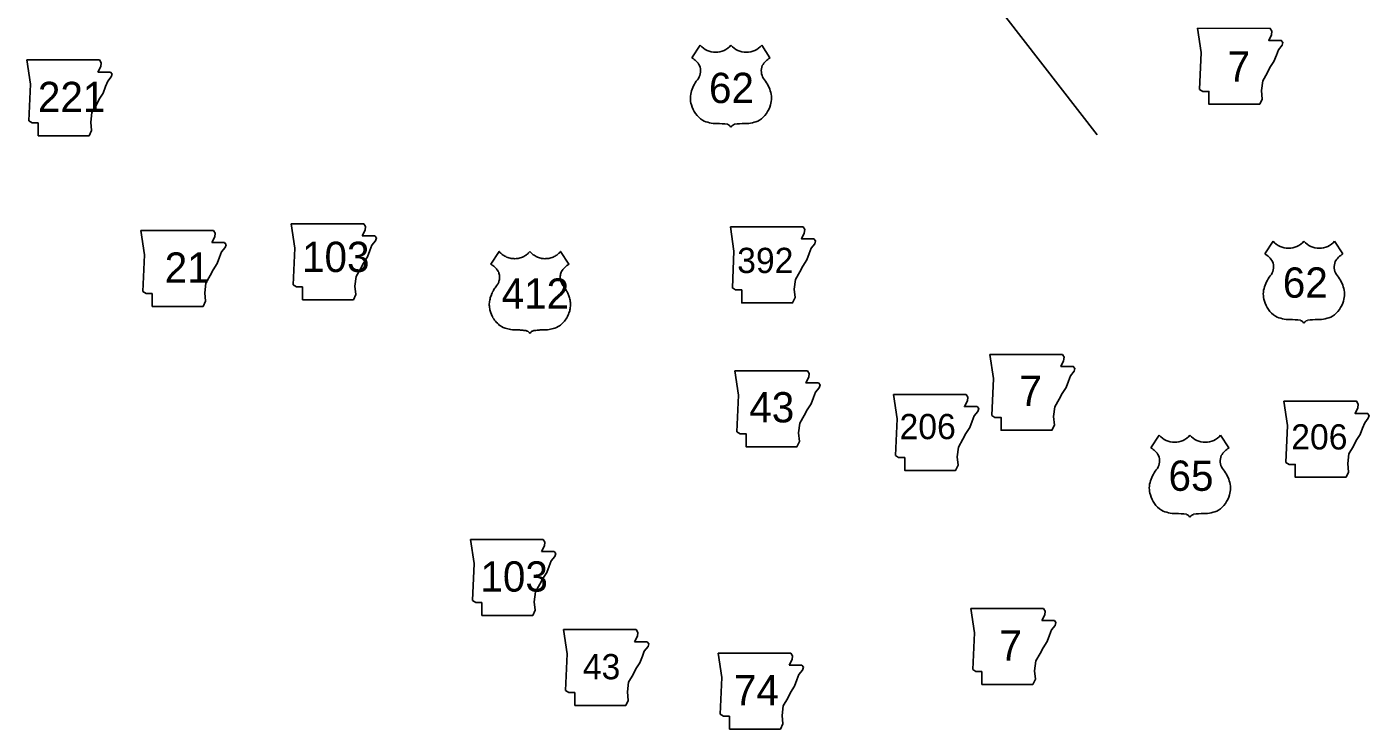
# Model space of a CAD drawing. Extents: x -819161 to 80911, y -6604 to 768454.
# Drawn here: x 41298 to 43405, y 4694 to 5796 of the extents above; entities that cross this region are included whole.
import ezdxf

# ---------------------------------------------------------------- set-up
doc = ezdxf.new("R2010")
doc.units = 0
for name, color, linetype in [('Default', 7, 'Continuous'), ('Level 21', 7, 'Continuous'), ('Level 22', 7, 'Continuous')]:
    doc.layers.add(name, color=color, linetype=linetype)

msp = doc.modelspace()

# ---------------------------------------------------------------- linework, layer by layer
at = {"layer": 'Default'}
msp.add_lwpolyline([(42312.2, 6485.2), (42978.2, 5626.8)], dxfattribs=at)
at = {"layer": 'Level 21'}
for p, q in [((41297.9, 5744.4), (41303.6, 5706.4)), ((41409.5, 5725.4), (41414, 5734.3)), ((41414.6, 5740), (41412, 5744.4)), ((41414, 5734.3), (41414.6, 5740)), ((41429.2, 5725.4), (41409.5, 5725.4)), ((41424.8, 5710.8), (41430.5, 5717.8)), ((41431.7, 5722.2), (41429.2, 5725.4)), ((41430.5, 5717.8), (41431.7, 5722.2)), ((41303.6, 5706.4), (41301, 5648.6)), ((41411.4, 5682.9), (41417.8, 5692.4)), ((41417.8, 5692.4), (41421.6, 5702.6)), ((41421.6, 5702.6), (41424.8, 5710.8)), ((41400, 5662), (41407, 5674)), ((41407, 5674), (41411.4, 5682.9)), ((41301, 5648.6), (41306.1, 5645.5)), ((41398.1, 5646.7), (41400, 5662)), ((41306.1, 5645.5), (41315.6, 5645.5)), ((41315.6, 5645.5), (41315.6, 5625.2)), ((41395.6, 5625.2), (41399.4, 5633.4)), ((41399.4, 5633.4), (41398.1, 5646.7)), ((41315.6, 5625.2), (41395.6, 5625.2)), ((41712.9, 5487.1), (41718.6, 5449)), ((41829.6, 5482.7), (41827, 5487.1)), ((41829, 5477), (41829.6, 5482.7)), ((41476.8, 5476.6), (41482.5, 5438.6)), ((41588.5, 5457.6), (41592.9, 5466.5)), ((41593.5, 5472.2), (41590.9, 5476.6)), ((41592.9, 5466.5), (41593.5, 5472.2)), ((41824.6, 5468.1), (41829, 5477)), ((41844.2, 5468.1), (41824.6, 5468.1)), ((41839.8, 5453.5), (41845.5, 5460.5)), ((41846.8, 5464.9), (41844.2, 5468.1)), ((41845.5, 5460.5), (41846.8, 5464.9)), ((41482.5, 5438.6), (41480, 5380.8)), ((41608.1, 5457.6), (41588.5, 5457.6)), ((41600.5, 5434.8), (41603.7, 5443)), ((41603.7, 5443), (41609.4, 5450)), ((41610.7, 5454.4), (41608.1, 5457.6)), ((41609.4, 5450), (41610.7, 5454.4)), ((41718.6, 5449), (41716.1, 5391.3)), ((41832.8, 5435.1), (41836.6, 5445.2)), ((41836.6, 5445.2), (41839.8, 5453.5)), ((41590.4, 5415.1), (41596.7, 5424.6)), ((41596.7, 5424.6), (41600.5, 5434.8)), ((41815, 5404.6), (41822, 5416.7)), ((41822, 5416.7), (41826.5, 5425.6)), ((41826.5, 5425.6), (41832.8, 5435.1)), ((41579, 5394.2), (41585.9, 5406.2)), ((41585.9, 5406.2), (41590.4, 5415.1)), ((41813.1, 5389.4), (41815, 5404.6)), ((41480, 5380.8), (41485.1, 5377.7)), ((41485.1, 5377.7), (41494.6, 5377.7)), ((41494.6, 5377.7), (41494.6, 5357.4)), ((41577.1, 5378.9), (41579, 5394.2)), ((41578.3, 5365.6), (41577.1, 5378.9)), ((41716.1, 5391.3), (41721.2, 5388.1)), ((41721.2, 5388.1), (41730.7, 5388.1)), ((41730.7, 5388.1), (41730.7, 5367.8)), ((41810.6, 5367.8), (41814.4, 5376.1)), ((41814.4, 5376.1), (41813.1, 5389.4)), ((41494.6, 5357.4), (41574.5, 5357.4)), ((41574.5, 5357.4), (41578.3, 5365.6)), ((41730.7, 5367.8), (41810.6, 5367.8)), ((41994.4, 4991.7), (42000.1, 4953.7)), ((42106.1, 4972.7), (42110.5, 4981.6)), ((42111.1, 4987.3), (42108.5, 4991.7)), ((42110.5, 4981.6), (42111.1, 4987.3)), ((42000.1, 4953.7), (41997.6, 4895.9)), ((42125.7, 4972.7), (42106.1, 4972.7)), ((42118.1, 4949.9), (42121.3, 4958.1)), ((42121.3, 4958.1), (42127, 4965.1)), ((42128.3, 4969.5), (42125.7, 4972.7)), ((42127, 4965.1), (42128.3, 4969.5)), ((42108, 4930.2), (42114.3, 4939.7)), ((42114.3, 4939.7), (42118.1, 4949.9)), ((42096.6, 4909.3), (42103.5, 4921.3)), ((42103.5, 4921.3), (42108, 4930.2)), ((41997.6, 4895.9), (42002.7, 4892.8)), ((42002.7, 4892.8), (42012.2, 4892.8)), ((42012.2, 4892.8), (42012.2, 4872.5)), ((42094.6, 4894), (42096.6, 4909.3)), ((42095.9, 4880.7), (42094.6, 4894)), ((42012.2, 4872.5), (42092.1, 4872.5)), ((42092.1, 4872.5), (42095.9, 4880.7)), ((42779.9, 4883.3), (42785.6, 4845.3)), ((42891.5, 4864.3), (42896, 4873.2)), ((42896.6, 4878.9), (42894, 4883.3)), ((42896, 4873.2), (42896.6, 4878.9)), ((42140.6, 4850.2), (42146.3, 4812.1)), ((42257.3, 4845.7), (42254.7, 4850.1)), ((42911.2, 4864.3), (42891.5, 4864.3)), ((42903.6, 4841.5), (42906.8, 4849.7)), ((42906.8, 4849.7), (42912.5, 4856.7)), ((42913.7, 4861.1), (42911.2, 4864.3)), ((42912.5, 4856.7), (42913.7, 4861.1)), ((42252.2, 4831.1), (42256.7, 4840)), ((42271.9, 4831.1), (42252.2, 4831.1)), ((42256.7, 4840), (42257.3, 4845.7)), ((42274.4, 4827.9), (42271.9, 4831.1)), ((42273.2, 4823.5), (42274.4, 4827.9)), ((42785.6, 4845.3), (42783.1, 4787.5)), ((42893.4, 4821.8), (42899.8, 4831.3)), ((42899.8, 4831.3), (42903.6, 4841.5)), ((42146.3, 4812.1), (42143.7, 4754.4)), ((42260.5, 4798.1), (42264.3, 4808.3)), ((42264.3, 4808.3), (42267.4, 4816.5)), ((42267.4, 4816.5), (42273.2, 4823.5)), ((42383.4, 4813.2), (42389.1, 4775.1)), ((42500.1, 4808.8), (42497.5, 4813.1)), ((42499.5, 4803), (42500.1, 4808.8)), ((42882, 4800.9), (42889, 4812.9)), ((42889, 4812.9), (42893.4, 4821.8)), ((42249.7, 4779.7), (42254.1, 4788.6)), ((42254.1, 4788.6), (42260.5, 4798.1)), ((42495, 4794.2), (42499.5, 4803)), ((42514.7, 4794.2), (42495, 4794.2)), ((42510.2, 4779.6), (42516, 4786.5)), ((42517.2, 4791), (42514.7, 4794.2)), ((42516, 4786.5), (42517.2, 4791)), ((42783.1, 4787.5), (42788.1, 4784.4)), ((42788.1, 4784.4), (42797.6, 4784.4)), ((42797.6, 4784.4), (42797.6, 4764.1)), ((42880.1, 4785.6), (42882, 4800.9)), ((42881.4, 4772.3), (42880.1, 4785.6)), ((42240.8, 4752.4), (42242.7, 4767.7)), ((42242.7, 4767.7), (42249.7, 4779.7)), ((42389.1, 4775.1), (42386.5, 4717.4)), ((42503.3, 4761.2), (42507.1, 4771.3)), ((42507.1, 4771.3), (42510.2, 4779.6)), ((42797.6, 4764.1), (42877.6, 4764.1)), ((42877.6, 4764.1), (42881.4, 4772.3)), ((42143.7, 4754.4), (42148.8, 4751.2)), ((42148.8, 4751.2), (42158.3, 4751.2)), ((42158.3, 4751.2), (42158.3, 4730.9)), ((42242.1, 4739.1), (42240.8, 4752.4)), ((42485.5, 4730.7), (42492.5, 4742.8)), ((42492.5, 4742.8), (42496.9, 4751.7)), ((42496.9, 4751.7), (42503.3, 4761.2)), ((42158.3, 4730.9), (42238.3, 4730.9)), ((42238.3, 4730.9), (42242.1, 4739.1)), ((42483.6, 4715.5), (42485.5, 4730.7)), ((42386.5, 4717.4), (42391.6, 4714.2)), ((42391.6, 4714.2), (42401.1, 4714.2)), ((42401.1, 4714.2), (42401.1, 4693.9)), ((42481.1, 4693.9), (42484.9, 4702.2)), ((42484.9, 4702.2), (42483.6, 4715.5)), ((42401.1, 4693.9), (42481.1, 4693.9))]:
    msp.add_line(p, q, dxfattribs=at)
for points in [[(43136.1, 5794), (43141.9, 5755.9), (43139.3, 5698.2), (43144.4, 5695), (43153.9, 5695), (43153.9, 5674.7), (43233.8, 5674.7), (43237.6, 5682.9), (43236.4, 5696.3), (43238.3, 5711.5), (43245.3, 5723.5), (43249.7, 5732.4), (43256, 5741.9), (43259.9, 5752.1), (43263, 5760.3), (43268.7, 5767.3), (43270, 5771.8), (43267.5, 5774.9), (43247.8, 5774.9), (43252.2, 5783.8), (43252.9, 5789.5), (43250.2, 5793.9)], [(42402.5, 5482.4), (42408.2, 5444.3), (42405.7, 5386.6), (42410.7, 5383.4), (42420.3, 5383.4), (42420.3, 5363.1), (42500.2, 5363.1), (42504, 5371.4), (42502.7, 5384.7), (42504.6, 5399.9), (42511.6, 5412), (42516.1, 5420.9), (42522.4, 5430.4), (42526.2, 5440.5), (42529.4, 5448.8), (42535.1, 5455.8), (42536.4, 5460.2), (42533.8, 5463.4), (42514.2, 5463.4), (42518.6, 5472.2), (42519.2, 5478), (42516.6, 5482.3)], [(42809.7, 5282.2), (42815.4, 5244.2), (42812.9, 5186.4), (42817.9, 5183.3), (42827.5, 5183.3), (42827.5, 5163), (42907.4, 5163), (42911.2, 5171.2), (42909.9, 5184.5), (42911.8, 5199.8), (42918.8, 5211.8), (42923.3, 5220.7), (42929.6, 5230.2), (42933.4, 5240.4), (42936.6, 5248.6), (42942.3, 5255.6), (42943.6, 5260), (42941, 5263.2), (42921.4, 5263.2), (42925.8, 5272.1), (42926.4, 5277.8), (42923.8, 5282.2)], [(42409.4, 5256.5), (42415.1, 5218.4), (42412.6, 5160.7), (42417.7, 5157.5), (42427.2, 5157.5), (42427.2, 5137.2), (42507.1, 5137.2), (42510.9, 5145.4), (42509.7, 5158.8), (42511.6, 5174), (42518.6, 5186.1), (42523, 5194.9), (42529.3, 5204.5), (42533.2, 5214.6), (42536.3, 5222.8), (42542, 5229.8), (42543.3, 5234.3), (42540.8, 5237.4), (42521.1, 5237.4), (42525.5, 5246.3), (42526.2, 5252), (42523.5, 5256.4)], [(42658.5, 5219.3), (42664.2, 5181.2), (42661.7, 5123.5), (42666.7, 5120.3), (42676.3, 5120.3), (42676.3, 5100), (42756.2, 5100), (42760, 5108.3), (42758.7, 5121.6), (42760.6, 5136.8), (42767.6, 5148.9), (42772, 5157.8), (42778.4, 5167.3), (42782.2, 5177.4), (42785.4, 5185.7), (42791.1, 5192.6), (42792.4, 5197.1), (42789.8, 5200.3), (42770.1, 5200.3), (42774.6, 5209.1), (42775.2, 5214.9), (42772.6, 5219.2)], [(43271.6, 5208.5), (43277.3, 5170.4), (43274.8, 5112.7), (43279.9, 5109.5), (43289.4, 5109.5), (43289.4, 5089.2), (43369.3, 5089.2), (43373.1, 5097.5), (43371.9, 5110.8), (43373.8, 5126), (43380.7, 5138.1), (43385.2, 5147), (43391.5, 5156.5), (43395.3, 5166.6), (43398.5, 5174.9), (43404.2, 5181.9), (43405.5, 5186.3), (43403, 5189.5), (43383.3, 5189.5), (43387.7, 5198.4), (43388.4, 5204.1), (43385.7, 5208.5)]]:
    msp.add_lwpolyline(points, close=True, dxfattribs=at)
for points in [[(41297.9, 5744.4), (41412, 5744.4)], [(41712.9, 5487.1), (41827, 5487.1)], [(41476.8, 5476.6), (41590.9, 5476.6)], [(41994.4, 4991.7), (42108.5, 4991.7)], [(42779.9, 4883.3), (42894, 4883.3)], [(42140.6, 4850.2), (42254.7, 4850.1)], [(42383.4, 4813.2), (42497.5, 4813.1)]]:
    msp.add_lwpolyline(points, dxfattribs=at)
at = {"layer": 'Level 22'}
for p, q in [((42355.1, 5767.7), (42342.2, 5747.6)), ((42451.7, 5767.7), (42464.6, 5747.6)), ((43254.8, 5459.9), (43241.8, 5439.8)), ((43351.3, 5459.9), (43364.3, 5439.8)), ((43075.8, 5155.4), (43062.8, 5135.3)), ((43172.3, 5155.4), (43185.3, 5135.3))]:
    msp.add_line(p, q, dxfattribs=at)
for points in [[(42087.8, 5443.6), (42086.8, 5442.5), (42085.8, 5441.5), (42084.8, 5440.5), (42083.6, 5439.5), (42082.5, 5438.7), (42081.1, 5437.7), (42079.7, 5436.8), (42078, 5435.9), (42075.9, 5434.9), (42074.3, 5434.3), (42072.5, 5433.7), (42070.8, 5433.3), (42069.3, 5432.9), (42067.7, 5432.7), (42066.2, 5432.5), (42064.1, 5432.4), (42062.5, 5432.5), (42061, 5432.6), (42059.7, 5432.7), (42058.3, 5432.9), (42056.5, 5433.3), (42054.9, 5433.7), (42052.9, 5434.3), (42051.2, 5435), (42049.7, 5435.7), (42048.3, 5436.4), (42047, 5437.2), (42045.6, 5438.1), (42044.3, 5439.1), (42043.2, 5440), (42042.2, 5440.9), (42041.2, 5441.8), (42040.3, 5442.8), (42039.5, 5443.7), (42026.5, 5423.6), (42027.4, 5423.1), (42028.5, 5422.3), (42029.6, 5421.6), (42031, 5420.5), (42032.1, 5419.6), (42033.1, 5418.6), (42034.1, 5417.6), (42035.1, 5416.5), (42035.9, 5415.6), (42036.6, 5414.6), (42037.3, 5413.6), (42038, 5412.5), (42038.7, 5411.2), (42039.2, 5409.7), (42039.6, 5408.1), (42039.9, 5406.5), (42040, 5404.9), (42040.1, 5403.4), (42040.1, 5402.1), (42040, 5400.9), (42039.8, 5399.6), (42039.5, 5398.3), (42039.2, 5396.9), (42038.8, 5395.7), (42038.2, 5394.3), (42037.4, 5392.5), (42036.5, 5391.1), (42035.5, 5389.9), (42034.2, 5388.3), (42033.2, 5386.8), (42032.2, 5385.4), (42031.3, 5384), (42030.6, 5382.7), (42029.9, 5381.6), (42029.2, 5380.2), (42028.4, 5378.5), (42027.7, 5376.9), (42027.2, 5375.7), (42026.7, 5374.2), (42026, 5372.3), (42025.5, 5370.8), (42025.1, 5369.1), (42024.6, 5367.1), (42024.3, 5365.4), (42024.1, 5363.5), (42024, 5361.5), (42024, 5359.7), (42024.1, 5357.8), (42024.3, 5355.7), (42024.6, 5353.6), (42025, 5352.1), (42025.3, 5350.7), (42025.8, 5349.2), (42026.4, 5347.3), (42027.2, 5345), (42028, 5343.3), (42028.8, 5341.5), (42029.8, 5339.8), (42031, 5337.8), (42032.2, 5336), (42033.5, 5334.4), (42034.9, 5332.8), (42036.7, 5331), (42038.2, 5329.6), (42039.7, 5328.2)], [(42087.8, 5443.6), (42088.7, 5442.5), (42089.7, 5441.5), (42090.8, 5440.5), (42091.9, 5439.5), (42093, 5438.7), (42094.4, 5437.7), (42095.8, 5436.8), (42097.5, 5435.9), (42099.6, 5434.9), (42101.2, 5434.3), (42103, 5433.7), (42104.7, 5433.3), (42106.2, 5432.9), (42107.9, 5432.7), (42109.3, 5432.5), (42111.4, 5432.4), (42113, 5432.5), (42114.5, 5432.6), (42115.9, 5432.7), (42117.3, 5432.9), (42119, 5433.3), (42120.6, 5433.7), (42122.6, 5434.3), (42124.3, 5435), (42125.8, 5435.7), (42127.2, 5436.4), (42128.5, 5437.2), (42129.9, 5438.1), (42131.2, 5439.1), (42132.3, 5440), (42133.3, 5440.9), (42134.3, 5441.8), (42135.2, 5442.8), (42136, 5443.7), (42149, 5423.6), (42148.1, 5423.1), (42147, 5422.3), (42145.9, 5421.6), (42144.5, 5420.5), (42143.4, 5419.6), (42142.4, 5418.6), (42141.4, 5417.6), (42140.4, 5416.5), (42139.6, 5415.6), (42138.9, 5414.6), (42138.2, 5413.6), (42137.5, 5412.5), (42136.8, 5411.2), (42136.3, 5409.7), (42135.9, 5408.1), (42135.6, 5406.5), (42135.5, 5404.9), (42135.4, 5403.4), (42135.5, 5402.1), (42135.5, 5400.9), (42135.7, 5399.6), (42136, 5398.3), (42136.3, 5396.9), (42136.7, 5395.7), (42137.3, 5394.3), (42138.1, 5392.5), (42139, 5391.1), (42140, 5389.9), (42141.3, 5388.3), (42142.3, 5386.8), (42143.3, 5385.4), (42144.2, 5384), (42144.9, 5382.7), (42145.6, 5381.6), (42146.3, 5380.2), (42147.1, 5378.5), (42147.8, 5376.9), (42148.3, 5375.7), (42148.8, 5374.2), (42149.5, 5372.3), (42150, 5370.8), (42150.5, 5369.1), (42150.9, 5367.1), (42151.2, 5365.4), (42151.4, 5363.5), (42151.5, 5361.5), (42151.5, 5359.7), (42151.4, 5357.8), (42151.2, 5355.7), (42150.9, 5353.6), (42150.5, 5352.1), (42150.2, 5350.7), (42149.7, 5349.2), (42149.1, 5347.3), (42148.3, 5345), (42147.5, 5343.3), (42146.7, 5341.5), (42145.7, 5339.8), (42144.5, 5337.8), (42143.3, 5336), (42142, 5334.4), (42140.7, 5332.8), (42138.9, 5331), (42137.3, 5329.6), (42135.8, 5328.2)], [(42039.7, 5328.2), (42041.4, 5327), (42043.3, 5325.7), (42045.8, 5324.6), (42048.7, 5323.5), (42051, 5322.8), (42053.1, 5322.2), (42055.5, 5321.6), (42057.7, 5321.2), (42060.2, 5320.9), (42063.2, 5320.6), (42065.5, 5320.5), (42067.5, 5320.6), (42069.4, 5320.5), (42071.4, 5320.5), (42073.2, 5320.4), (42074.8, 5320.3), (42076.4, 5320.1), (42078.4, 5319.9), (42080.4, 5319.7), (42081.5, 5319.5), (42082.5, 5319.3), (42083.7, 5318.8), (42084.4, 5318.5), (42085, 5318.1), (42085.8, 5317.4), (42086.6, 5316.6), (42087.2, 5315.8), (42087.8, 5314.9)], [(42135.8, 5328.2), (42134.1, 5327), (42132.2, 5325.7), (42129.7, 5324.6), (42126.9, 5323.5), (42124.5, 5322.8), (42122.4, 5322.2), (42120, 5321.6), (42117.8, 5321.2), (42115.4, 5320.9), (42112.3, 5320.6), (42110, 5320.5), (42108, 5320.6), (42106.1, 5320.5), (42104.1, 5320.5), (42102.3, 5320.4), (42100.7, 5320.3), (42099.1, 5320.1), (42097.1, 5319.9), (42095.2, 5319.7), (42094, 5319.5), (42093, 5319.3), (42091.8, 5318.8), (42091.1, 5318.5), (42090.5, 5318.1), (42089.7, 5317.4), (42089, 5316.6), (42088.3, 5315.8), (42087.8, 5314.9)]]:
    msp.add_lwpolyline(points, dxfattribs=at)
for centre, radius, start, end in [((42379.3, 5788), 31.6, 220.075, 319.6701), ((42427.5, 5788), 31.6, 220.3299, 319.925), ((42325.2, 5718.4), 33.7, 30.7809, 59.9883), ((42332.6, 5727.3), 23.1, 328.8105, 21.2108), ((42474.2, 5727.3), 23.1, 158.7892, 211.1895), ((42481.6, 5718.4), 33.7, 120.0117, 149.2191), ((42393.1, 5679.9), 53.9, 138.9565, 162.6913), ((42413.7, 5679.9), 53.9, 17.3087, 41.0435), ((42375.3, 5684.4), 35.6, 160.9576, 197.3819), ((42431.5, 5684.4), 35.6, 342.6181, 19.0424), ((42381.1, 5684.5), 41.2, 195.1074, 237.1312), ((42425.7, 5684.5), 41.2, 302.8688, 344.8926), ((42381.8, 5697.4), 53, 244.0771, 269.5779), ((42425, 5697.4), 53, 270.4221, 295.9229), ((42383.1, 5547.5), 97, 81.1942, 90.9539), ((42395.2, 5634.5), 9.29, 28.0342, 72.9864), ((42411.6, 5634.5), 9.29, 107.0136, 151.9658), ((42423.7, 5547.5), 97, 89.0461, 98.8058), ((43278.9, 5480.3), 31.6, 220.075, 319.6701), ((43327.1, 5480.3), 31.6, 220.3299, 319.925), ((43224.8, 5410.7), 33.7, 30.7809, 59.9883), ((43381.2, 5410.7), 33.7, 120.0117, 149.2191), ((43232.2, 5419.6), 23.1, 328.8105, 21.2108), ((43373.8, 5419.6), 23.1, 158.7892, 211.1895), ((43292.7, 5372.2), 53.9, 138.9565, 162.6913), ((43313.4, 5372.2), 53.9, 17.3087, 41.0435), ((43274.9, 5376.6), 35.6, 160.9576, 197.3819), ((43331.2, 5376.6), 35.6, 342.6181, 19.0424), ((43280.7, 5376.7), 41.2, 195.1074, 237.1312), ((43325.4, 5376.7), 41.2, 302.8688, 344.8926), ((43281.5, 5389.7), 53, 244.0771, 269.5779), ((43282.7, 5239.8), 97, 81.1942, 90.9539), ((43294.8, 5326.7), 9.29, 28.0342, 72.9864), ((43311.2, 5326.7), 9.29, 107.0136, 151.9658), ((43323.4, 5239.8), 97, 89.0461, 98.8058), ((43324.6, 5389.7), 53, 270.4221, 295.9229), ((43100, 5175.8), 31.6, 220.075, 319.6701), ((43148.1, 5175.8), 31.6, 220.3299, 319.925), ((43045.9, 5106.2), 33.7, 30.7809, 59.9883), ((43053.3, 5115.1), 23.1, 328.8105, 21.2108), ((43194.8, 5115.1), 23.1, 158.7892, 211.1895), ((43202.3, 5106.2), 33.7, 120.0117, 149.2191), ((43113.7, 5067.7), 53.9, 138.9565, 162.6913), ((43134.4, 5067.7), 53.9, 17.3087, 41.0435), ((43095.9, 5072.1), 35.6, 160.9576, 197.3819), ((43152.2, 5072.1), 35.6, 342.6181, 19.0424), ((43101.7, 5072.2), 41.2, 195.1074, 237.1312), ((43146.4, 5072.2), 41.2, 302.8688, 344.8926), ((43102.5, 5085.2), 53, 244.0771, 269.5779), ((43145.6, 5085.2), 53, 270.4221, 295.9229), ((43103.7, 4935.3), 97, 81.1942, 90.9539), ((43115.9, 5022.2), 9.29, 28.0342, 72.9864), ((43132.3, 5022.2), 9.29, 107.0136, 151.9658), ((43144.4, 4935.3), 97, 89.0461, 98.8058)]:
    msp.add_arc(centre, radius, start, end, dxfattribs=at)

# ---------------------------------------------------------------- texts
at = {"layer": 'Level 21'}
for s, height, p in [('7', 47.5, (43183.3, 5710.3)), ('221', 47.52, (41315.2, 5662.5)), ('103', 47.52, (41729.9, 5411.5)), ('21', 47.52, (41514.3, 5394.7)), ('392', 39.6, (42413.2, 5409.9)), ('7', 47.5, (42856.3, 5201.2)), ('43', 47.52, (42432.2, 5175.4)), ('206', 39.6, (42668.1, 5149.1)), ('206', 39.6, (43283.1, 5132.9)), ('103', 47.52, (42010, 4909.8)), ('7', 47.5, (42824.9, 4801.4)), ('43', 39.6, (42170.8, 4772.2)), ('74', 47.52, (42408.1, 4731.3))]:
    msp.add_text(s, height=height, dxfattribs=at).set_placement(p)
at = {"layer": 'Level 22'}
for s, p in [('62', (42368.9, 5676.7)), ('62', (43269.9, 5371.2)), ('412', (42043.3, 5353.9)), ('65', (43090.4, 5068))]:
    msp.add_text(s, height=47.52, dxfattribs=at).set_placement(p)

doc.saveas('drawing.dxf')
